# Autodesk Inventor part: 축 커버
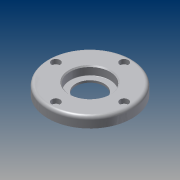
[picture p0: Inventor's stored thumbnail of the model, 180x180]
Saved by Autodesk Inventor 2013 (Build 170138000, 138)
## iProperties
Created: 2013-06
Part Number: 축 커버
Document SubType Name: Modeling
Designer: SeoGD™[esajin.kr]
Density: 2.71 g/cm^3
Material: 알루미늄 6061
Mass: 111.18 g
Surface Area: 133.703 cm^2
Volume: 41.026 cm^3
Author: SeoGD™[esajin.kr]
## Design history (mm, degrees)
sketch "스케치1"
  geometry: C1 r 40 at (0, 0) reference; C2 r 26 at (0, 0) reference; 1 further point
  node "참조1"
  node "참조2"
extrude "돌출1" new body sketch "스케치1" distance "d0" = 10; taper "d1" = 0 deg
extrude "돌출2" join sketch "스케치1" distance "d2" = 3; taper "d3" = 0 deg
hole "구멍1" diameter "d6" = 27; stored, may be unused: countersink angle "d10" = 90 deg, drill point angle "d12" = 118 deg; dims "d4" = 10, "d5" = 10, "d7" = 6, "d8" = 38, "d9" = 8, "d11" = 8
sketch "스케치2"
  geometry: C1 r 20 at (0, 0); 1 further point
  constraints: 1 centre point, 1 coincident
  dimensions: "d13" = 40 diameter of C1
extrude "돌출3" cut sketch "스케치2" distance "d14" = 3; taper "d15" = 0 deg
sketch "스케치3"
  geometry: C1 r 1.621 at (0, 32.5) reference; 1 further point
hole "구멍2" sketch "스케치3" at (0, 32.5) diameter "d16" = 4.5; stored, may be unused: countersink angle "d20" = 90 deg, drill point angle "d22" = 118 deg; dims "d17" = 6, "d18" = 8, "d19" = 4.4, "d21" = 8
fillet "모깎기1" dims "d26" = 3, "d27" = 0.3
chamfer "모따기1" distance "d28" = 1; stored, may be unused: second distance "d29" = 2, angle "d30" = 45 deg
node "솔리드1"
pattern_circular "원형 패턴1" dims angle "d24" = 360 deg
node "참조3"
